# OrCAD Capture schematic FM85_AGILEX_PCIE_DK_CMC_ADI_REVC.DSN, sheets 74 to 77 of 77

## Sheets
74 PWR -VCCCLK_GXR: size B
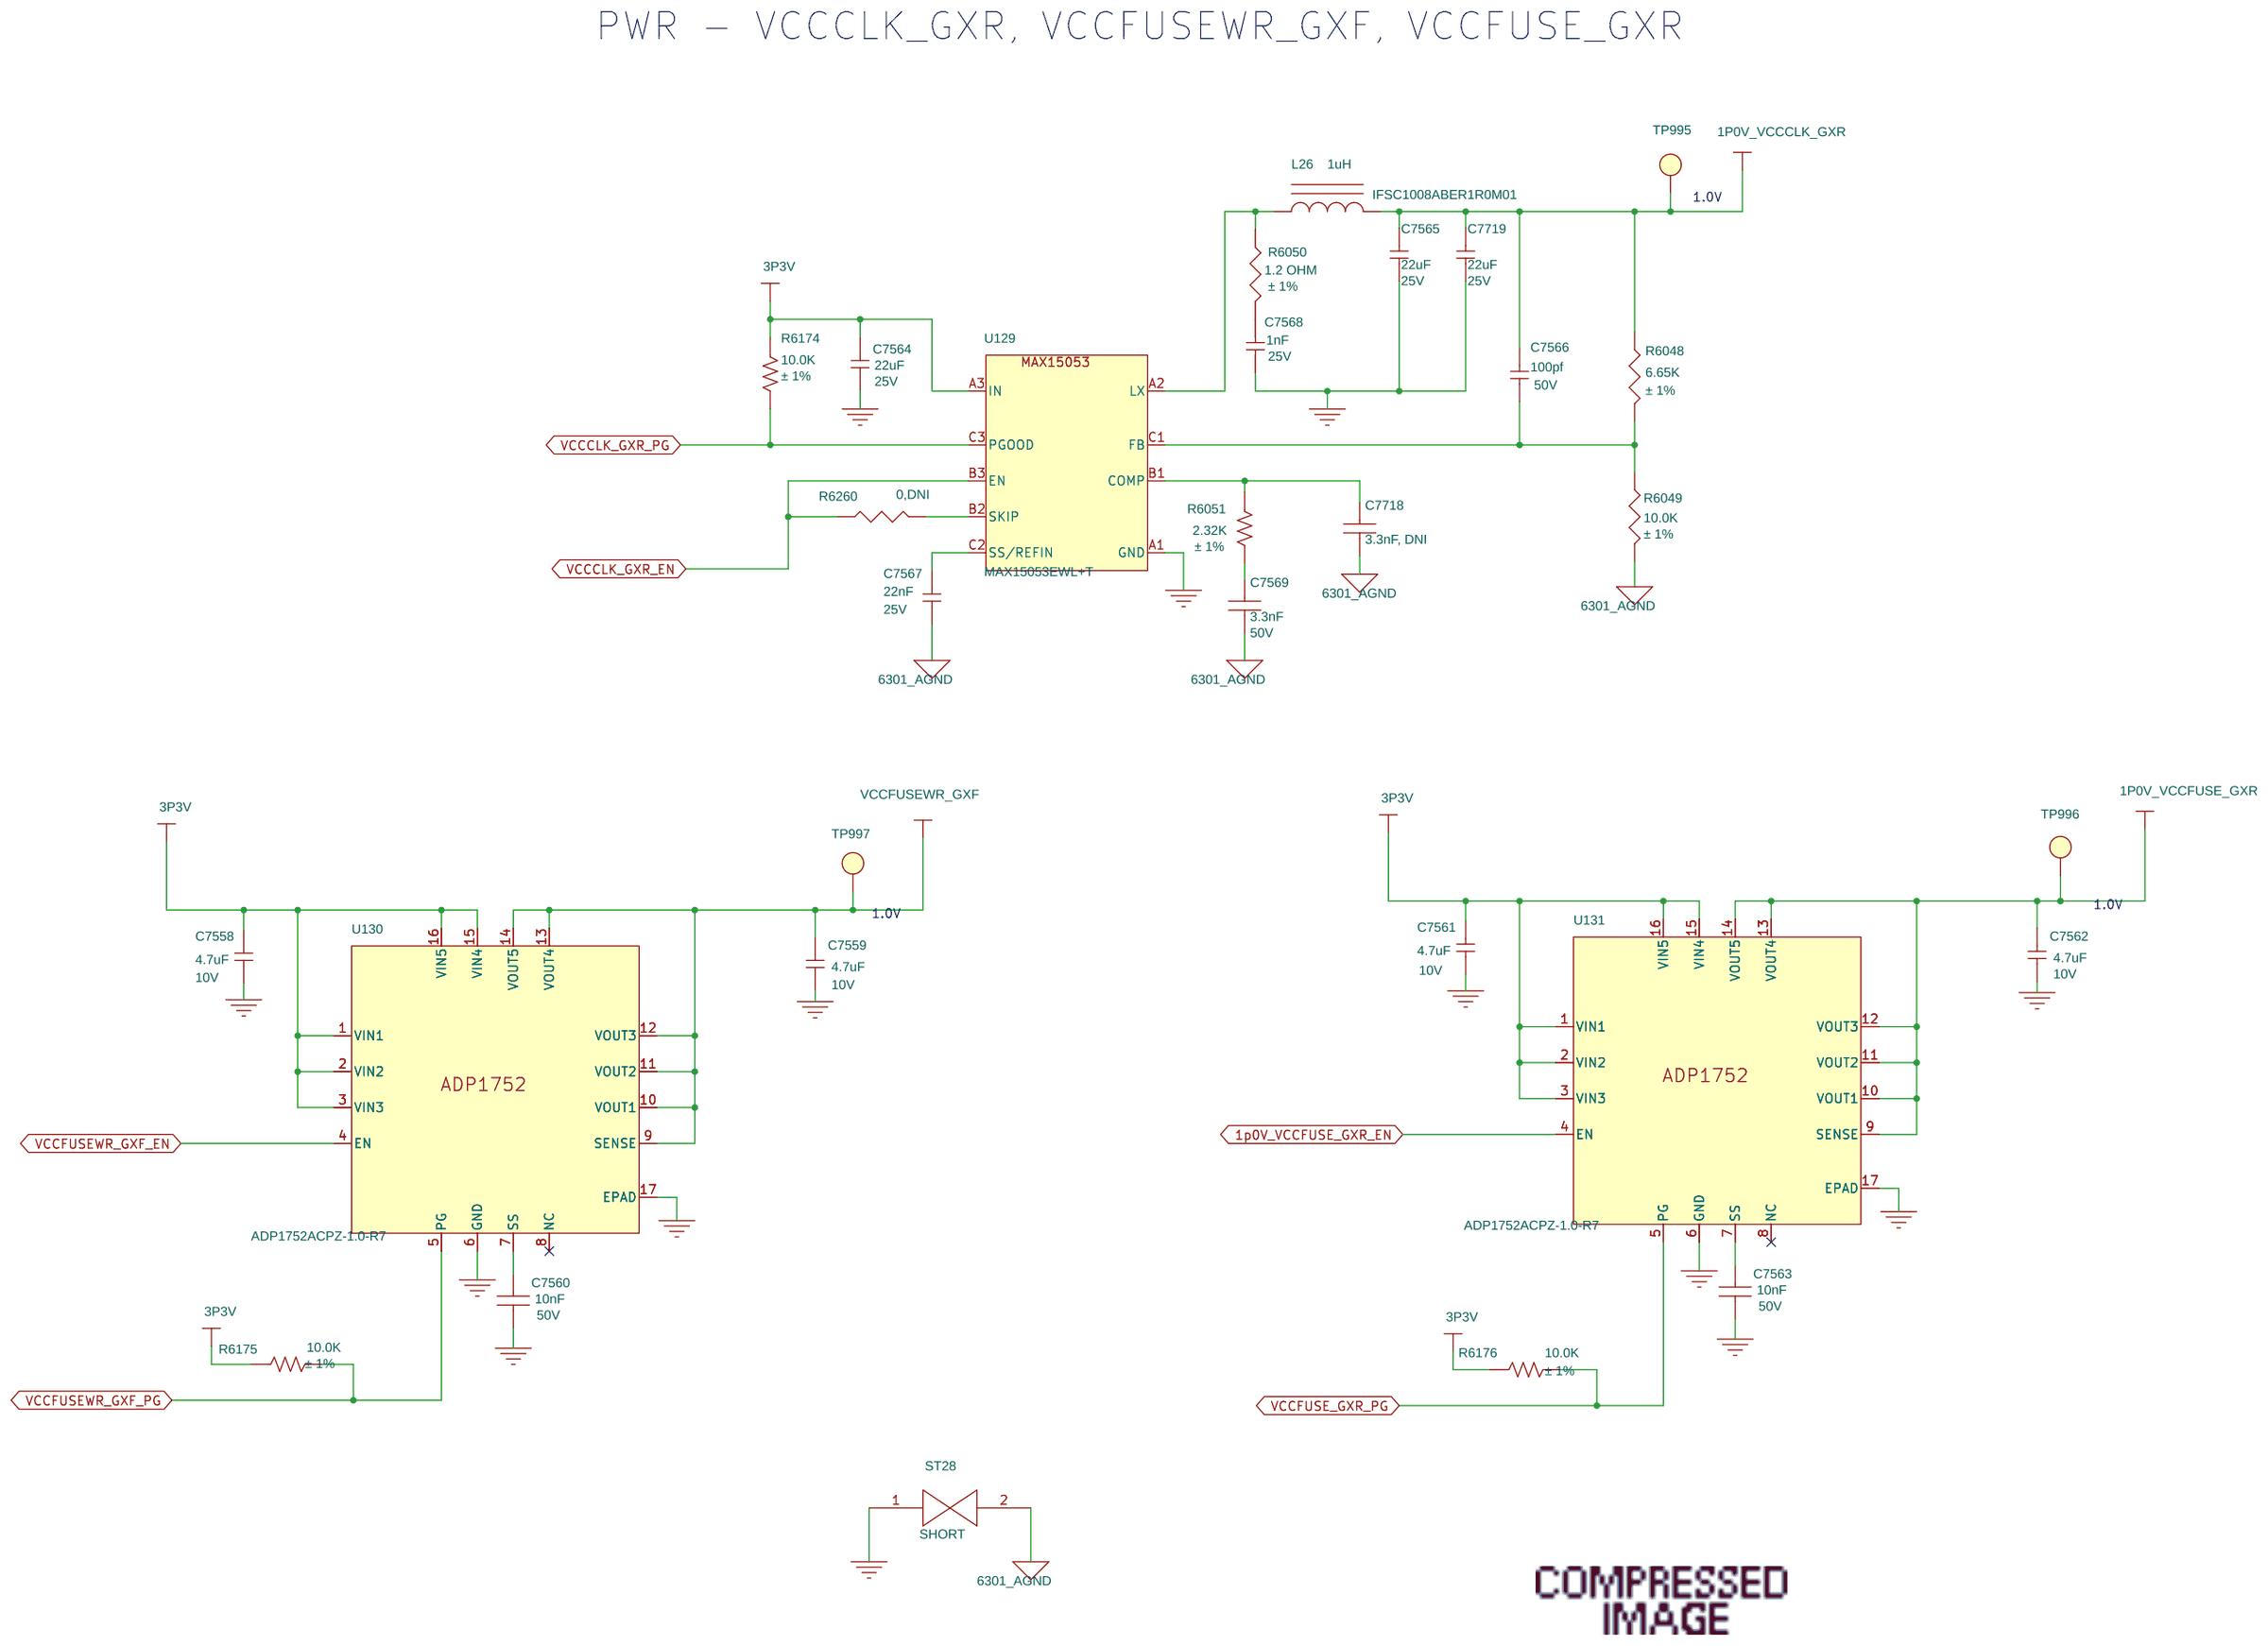
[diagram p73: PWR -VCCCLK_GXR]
75 Decoupling Caps 1: size B
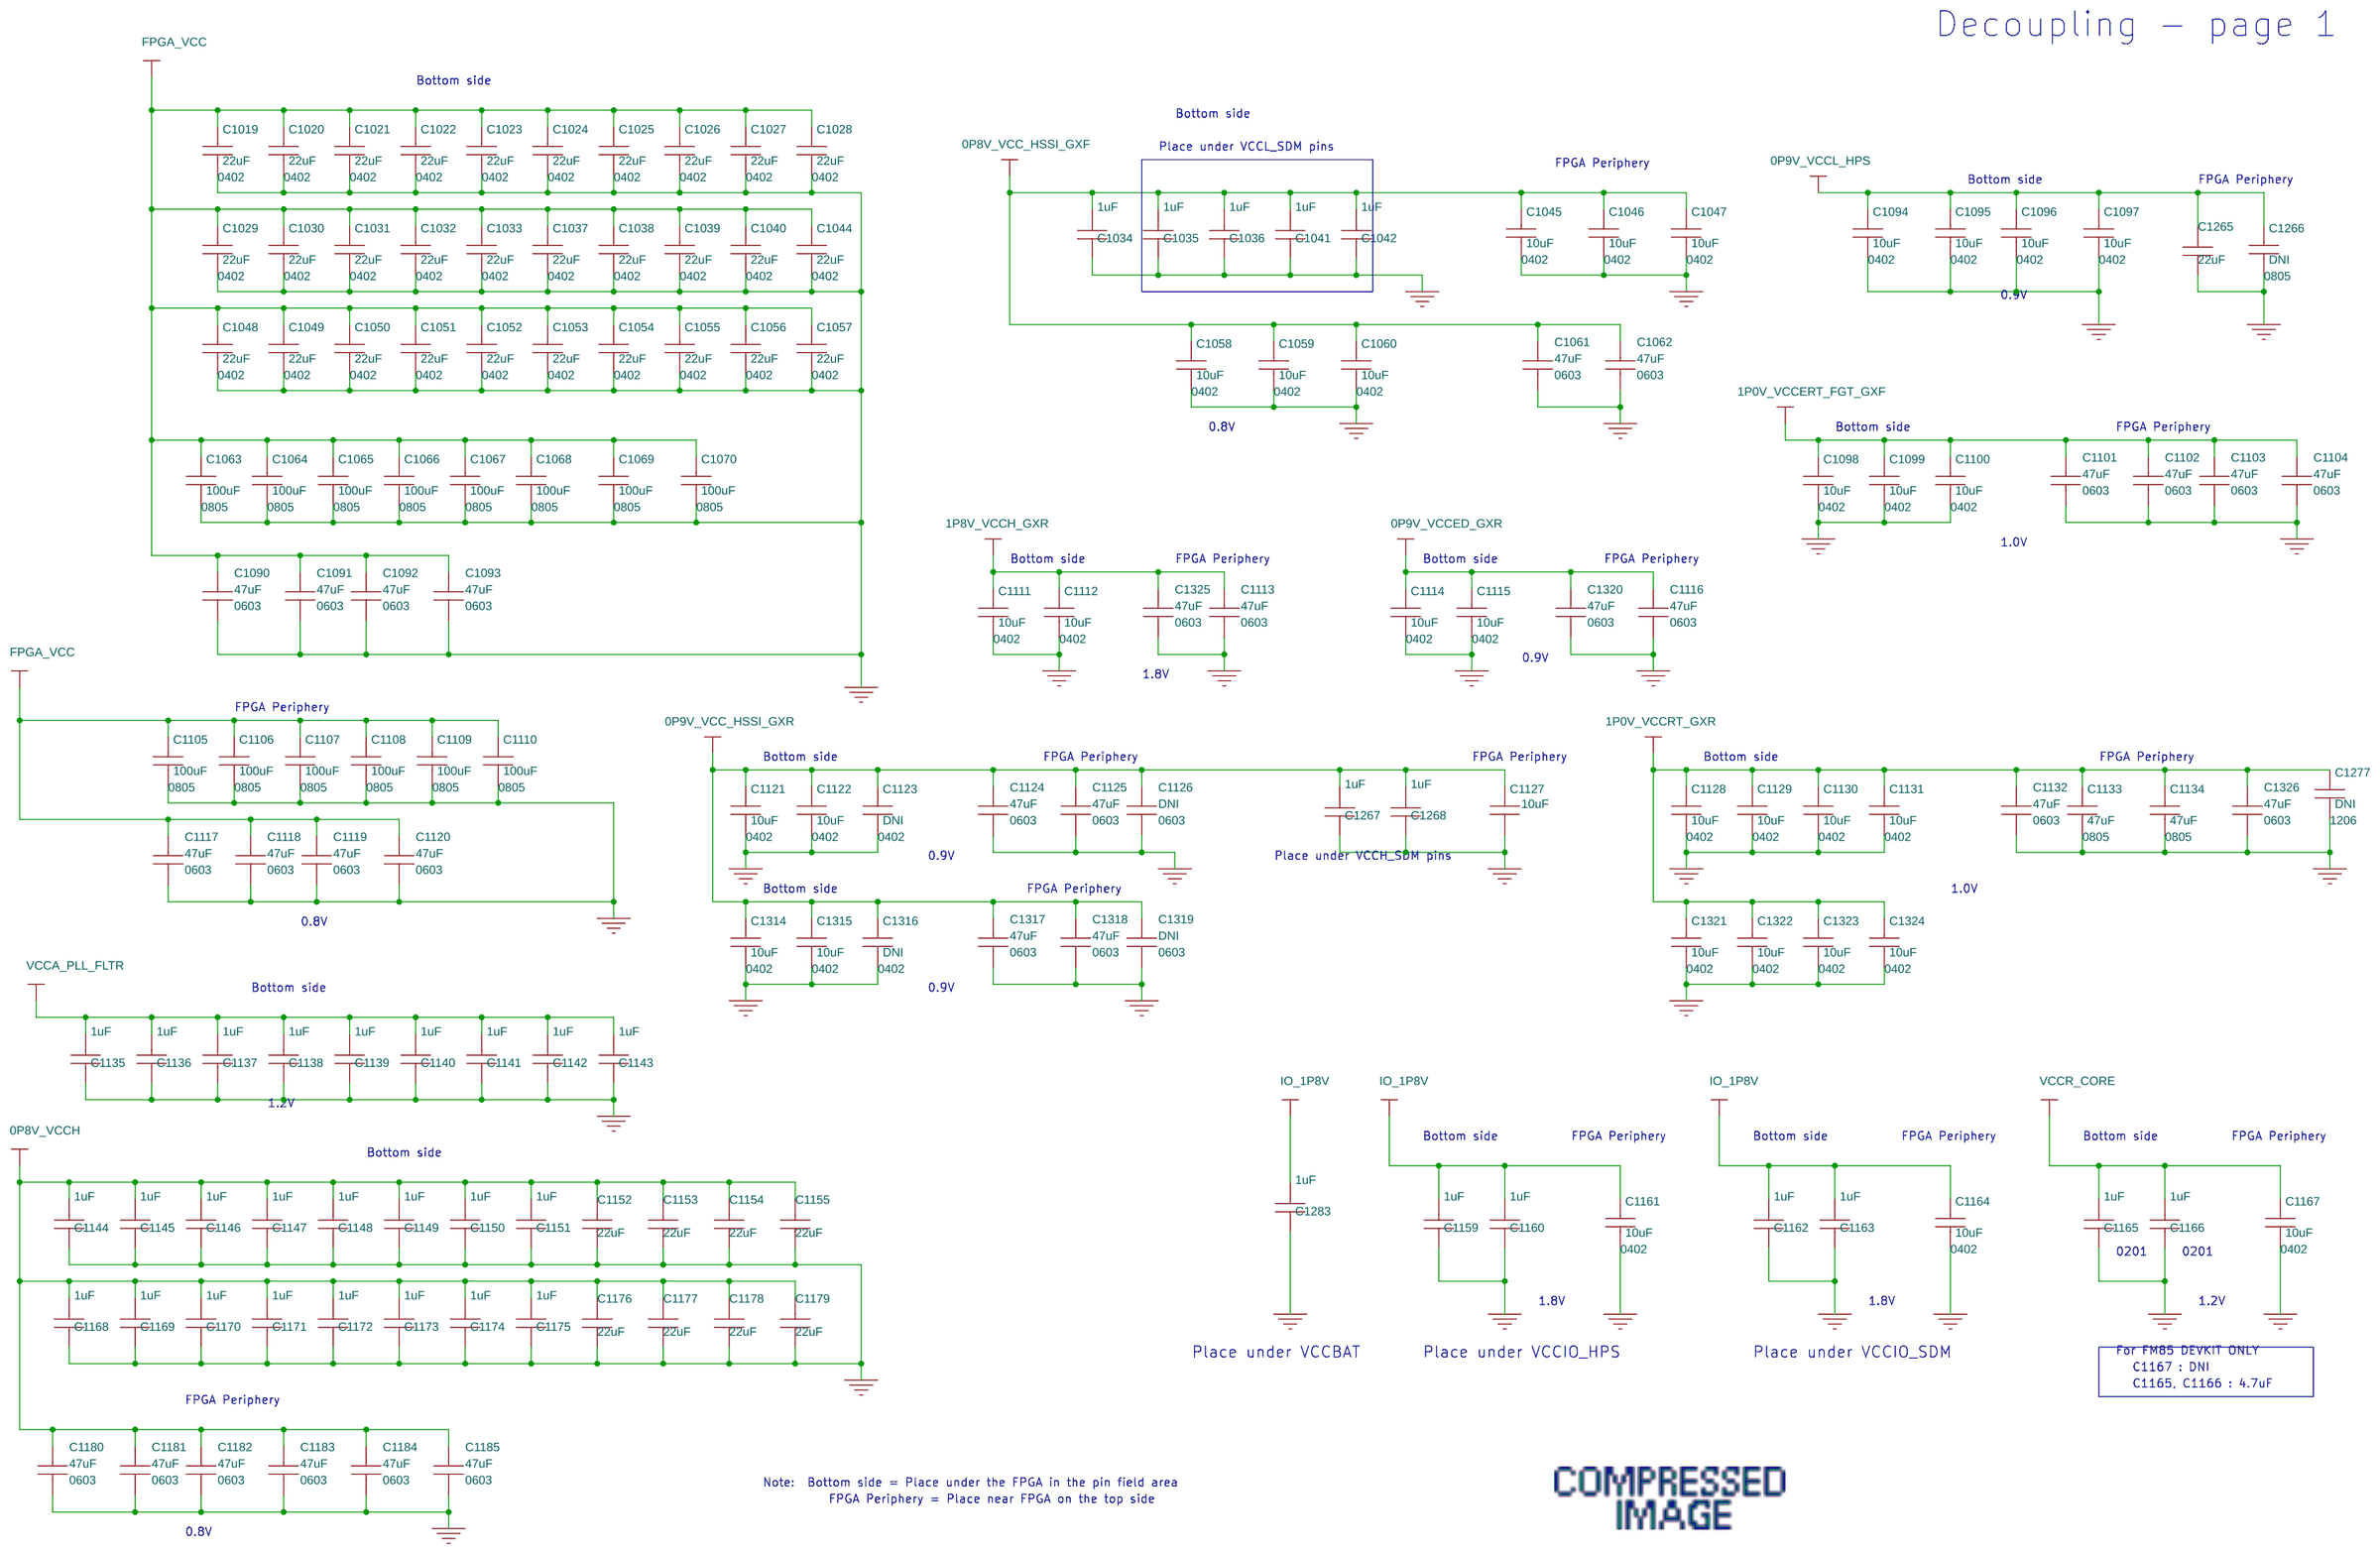
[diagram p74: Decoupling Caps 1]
76 Decoupling Caps 2: size B
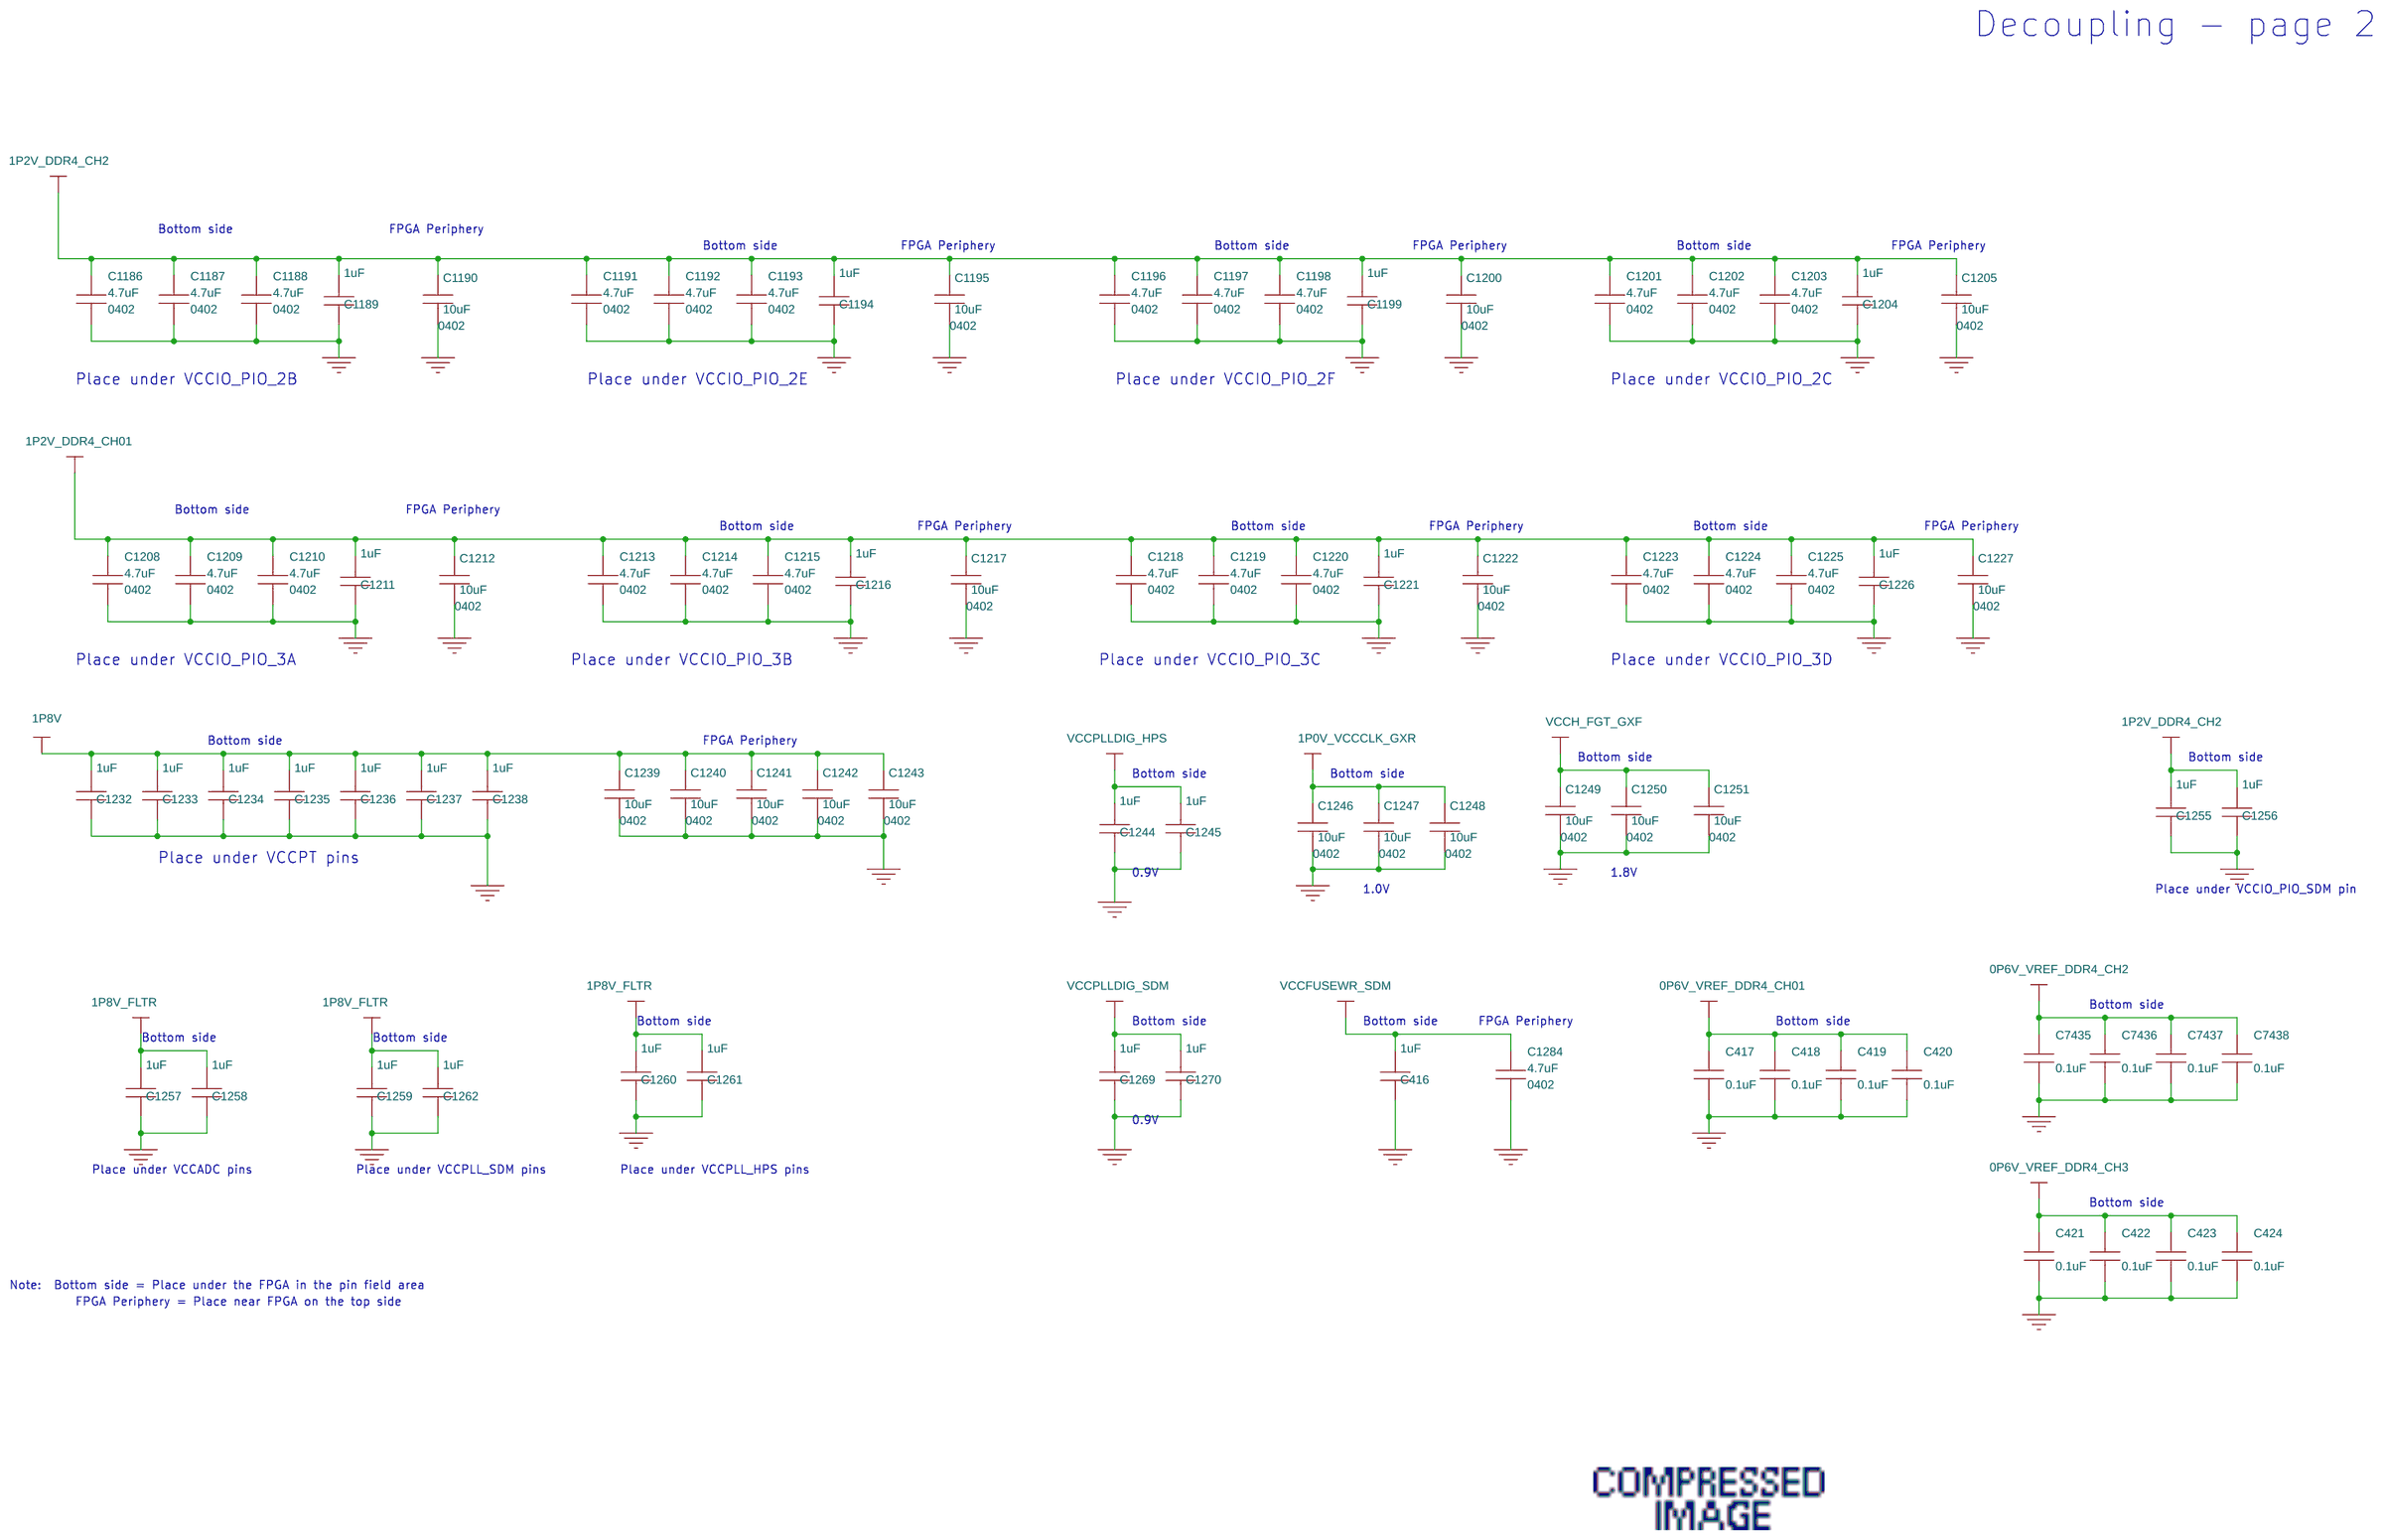
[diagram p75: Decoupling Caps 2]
77 Decoupling Caps 3 &Lev_Shtr: size B
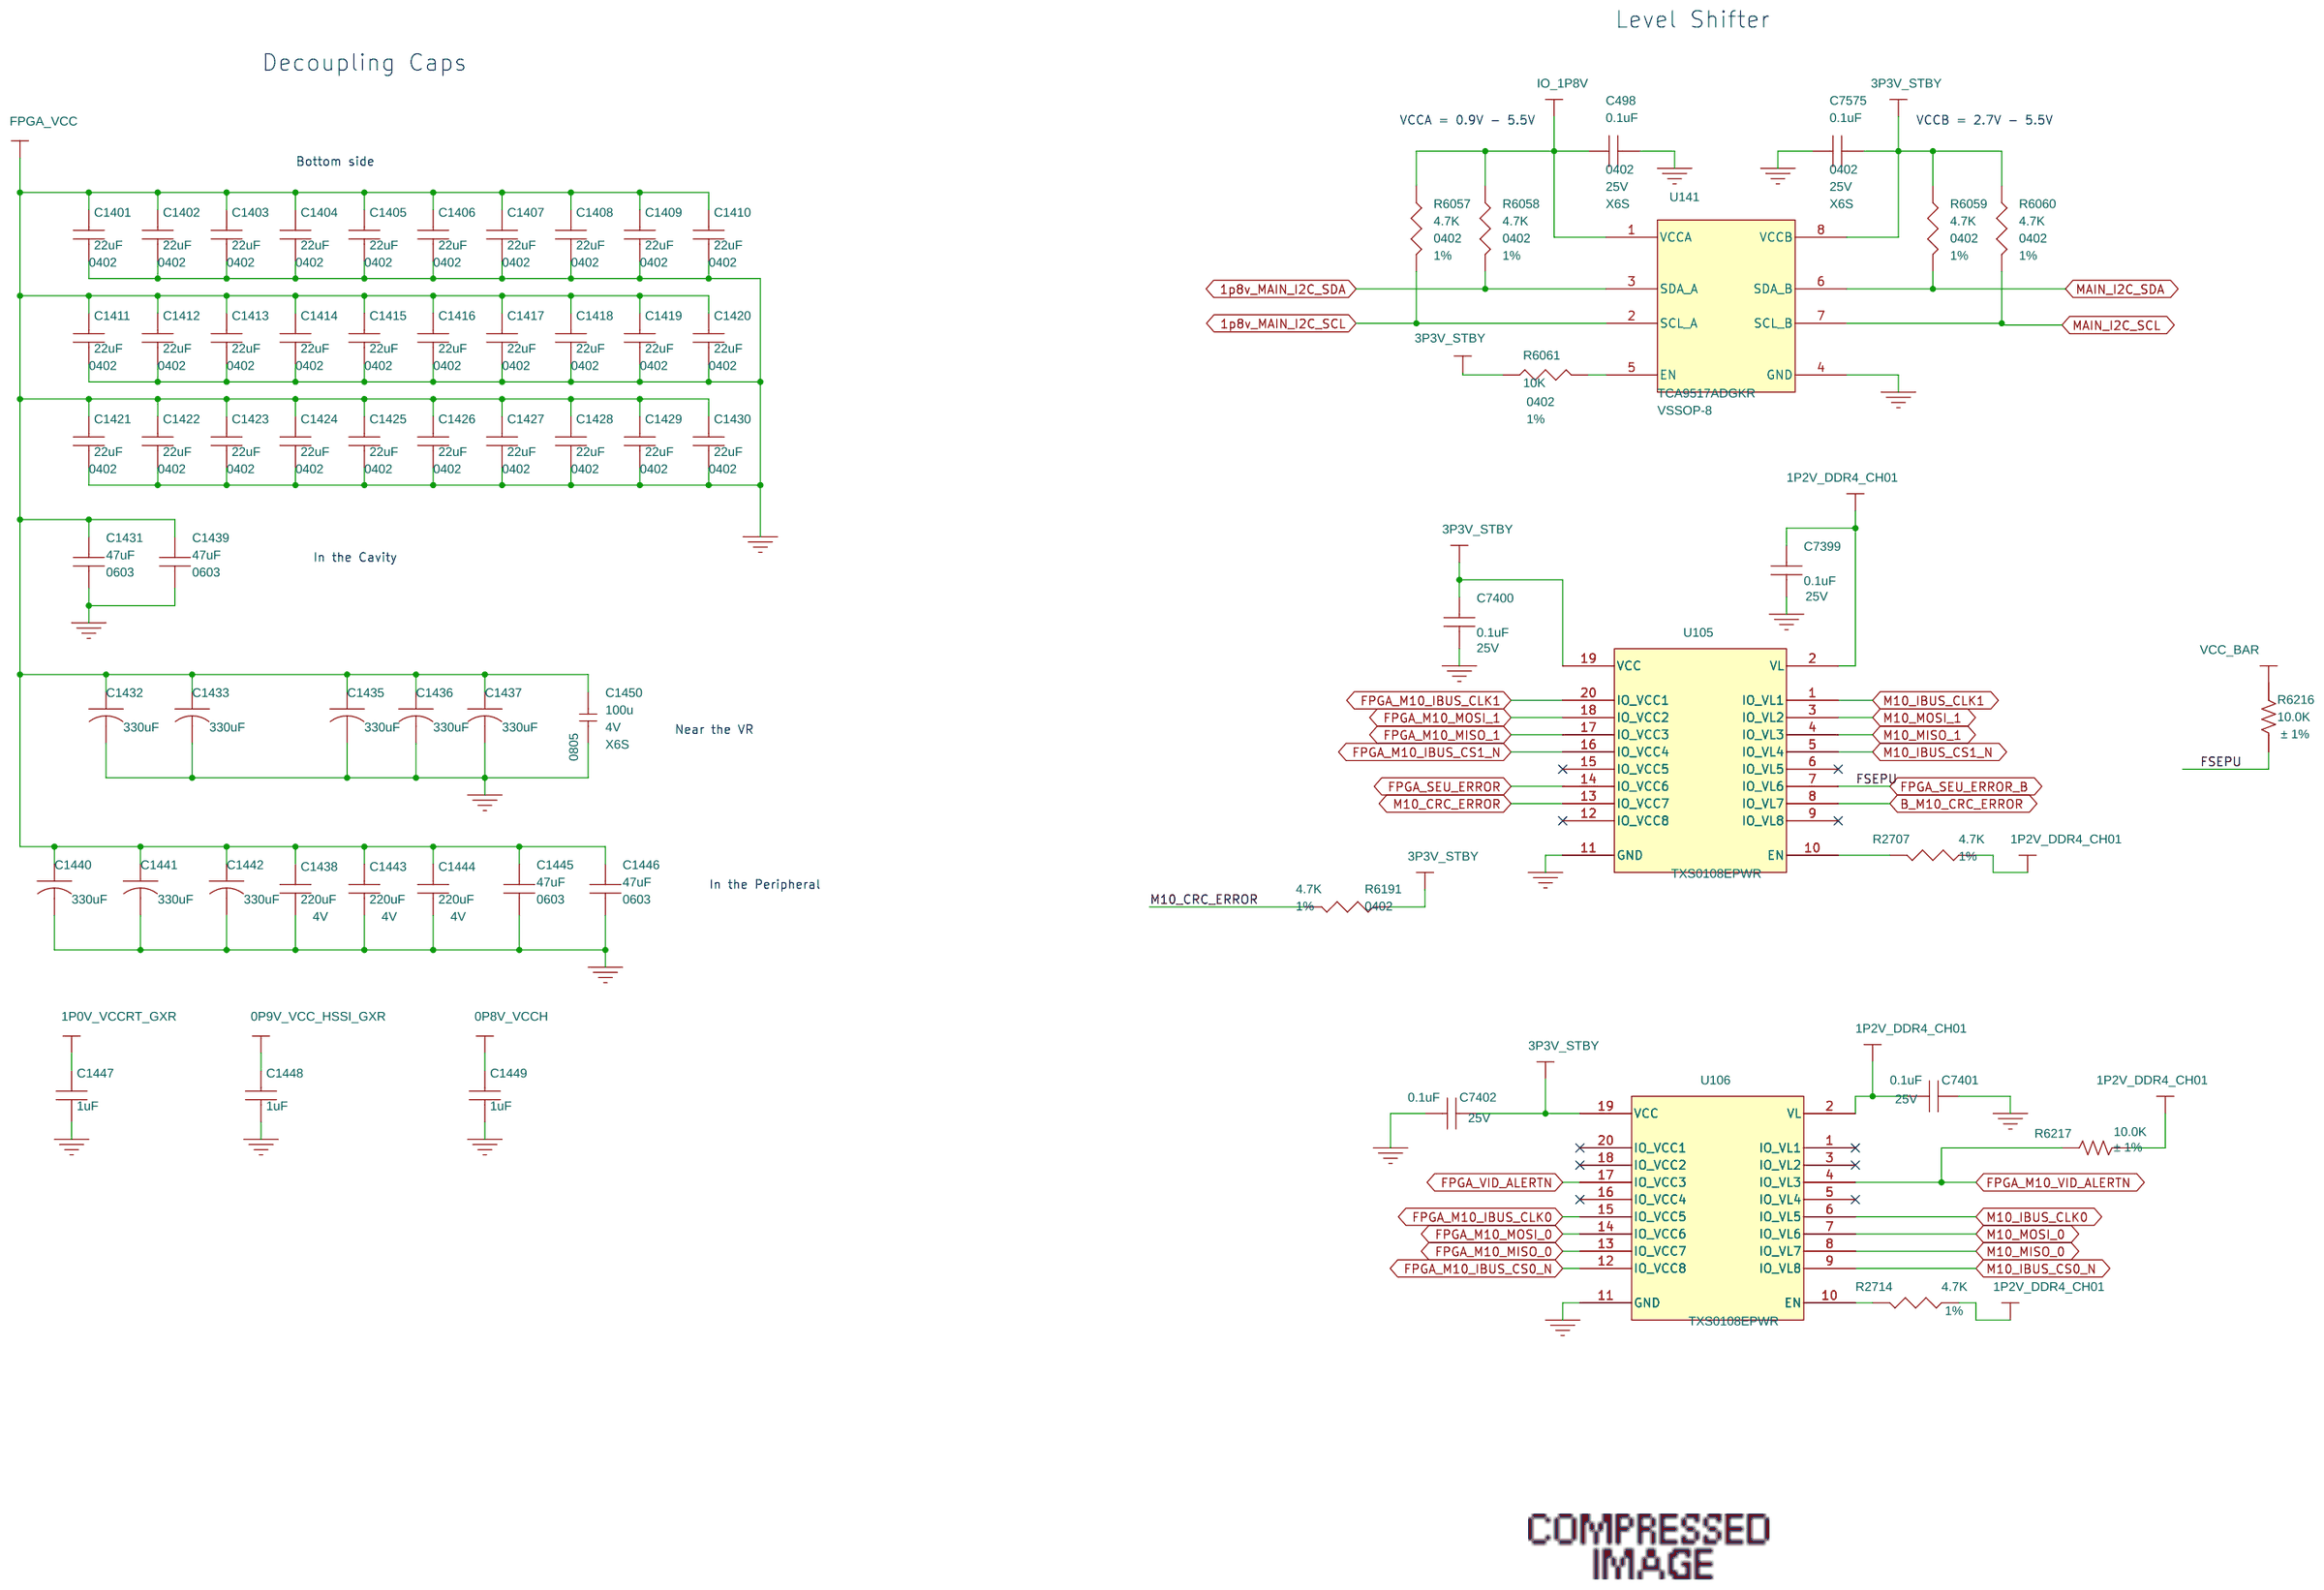
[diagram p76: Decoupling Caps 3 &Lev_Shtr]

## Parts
sheet Decoupling Caps 1
C1019  22uF  [0402]
C1020  22uF  [0402]
C1021  22uF  [0402]
C1022  22uF  [0402]
C1023  22uF  [0402]
C1024  22uF  [0402]
C1025  22uF  [0402]
C1026  22uF  [0402]
C1027  22uF  [0402]
C1028  22uF  [0402]
C1029  22uF  [0402]
C1030  22uF  [0402]
C1031  22uF  [0402]
C1032  22uF  [0402]
C1033  22uF  [0402]
C1034  1uF  [0201]
C1035  1uF  [0201]
C1036  1uF  [0201]
C1037  22uF  [0402]
C1038  22uF  [0402]
C1039  22uF  [0402]
C1040  22uF  [0402]
C1041  1uF  [0201]
C1042  1uF  [0201]
C1044  22uF  [0402]
C1045  10uF  [0402]
C1046  10uF  [0402]
C1047  10uF  [0402]
C1048  22uF  [0402]
C1049  22uF  [0402]
C1050  22uF  [0402]
C1051  22uF  [0402]
C1052  22uF  [0402]
C1053  22uF  [0402]
C1054  22uF  [0402]
C1055  22uF  [0402]
C1056  22uF  [0402]
C1057  22uF  [0402]
C1058  10uF  [0402]
C1059  10uF  [0402]
C1060  10uF  [0402]
C1061  47uF  [0603]
C1062  47uF  [0603]
C1063  100uF  [0805]
C1064  100uF  [0805]
C1065  100uF  [0805]
C1066  100uF  [0805]
C1067  100uF  [0805]
C1068  100uF  [0805]
C1069  100uF  [0805]
C1070  100uF  [0805]
C1090  47uF  [0603]
C1091  47uF  [0603]
C1092  47uF  [0603]
C1093  47uF  [0603]
C1094  10uF  [0402]
C1095  10uF  [0402]
C1096  10uF  [0402]
C1097  10uF  [0402]
C1098  10uF  [0402]
C1099  10uF  [0402]
C1100  10uF  [0402]
C1101  47uF  [0603]
C1102  47uF  [0603]
C1103  47uF  [0603]
C1104  47uF  [0603]
C1105  100uF  [0805]
C1106  100uF  [0805]
C1107  100uF  [0805]
C1108  100uF  [0805]
C1109  100uF  [0805]
C1110  100uF  [0805]
C1111  10uF  [0402]
C1112  10uF  [0402]
C1113  47uF  [0603]
C1114  10uF  [0402]
C1115  10uF  [0402]
C1116  47uF  [0603]
C1117  47uF  [0603]
C1118  47uF  [0603]
C1119  47uF  [0603]
C1120  47uF  [0603]
C1121  10uF  [0402]
C1122  10uF  [0402]
C1123  DNI  [0402]
C1124  47uF  [0603]
C1125  47uF  [0603]
C1126  DNI  [0603]
C1127  10uF  [0402]
C1128  10uF  [0402]
C1129  10uF  [0402]
C1130  10uF  [0402]
C1131  10uF  [0402]
C1132  47uF  [0603]
C1133  47uF  [0805]
C1134  47uF  [0805]
C1135  1uF  [0201]
C1136  1uF  [0201]
C1137  1uF  [0201]
C1138  1uF  [0201]
C1139  1uF  [0201]
C1140  1uF  [0201]
C1141  1uF  [0201]
C1142  1uF  [0201]
C1143  1uF  [0201]
C1144  1uF  [0201]
C1145  1uF  [0201]
C1146  1uF  [0201]
C1147  1uF  [0201]
C1148  1uF  [0201]
C1149  1uF  [0201]
C1150  1uF  [0201]
C1151  1uF  [0201]
C1152  22uF  [0603]
C1153  22uF  [0603]
C1154  22uF  [0603]
C1155  22uF  [0603]
C1159  1uF  [0201]
C1160  1uF  [0201]
C1161  10uF  [0402]
C1162  1uF  [0201]
C1163  1uF  [0201]
C1164  10uF  [0402]
C1165  1uF  [0201]
C1166  1uF  [0201]
C1167  10uF  [0402]
C1168  1uF  [0201]
C1169  1uF  [0201]
C1170  1uF  [0201]
C1171  1uF  [0201]
C1172  1uF  [0201]
C1173  1uF  [0201]
C1174  1uF  [0201]
C1175  1uF  [0201]
C1176  22uF  [0603]
C1177  22uF  [0603]
C1178  22uF  [0603]
C1179  22uF  [0603]
C1180  47uF  [0603]
C1181  47uF  [0603]
C1182  47uF  [0603]
C1183  47uF  [0603]
C1184  47uF  [0603]
C1185  47uF  [0603]
C1265  22uF  [0603]
C1266  DNI  [0805]
C1267  1uF  [0201]
C1268  1uF  [0201]
C1277  DNI  [1206]
C1283  1uF  [0201]
C1314  10uF  [0402]
C1315  10uF  [0402]
C1316  DNI  [0402]
C1317  47uF  [0603]
C1318  47uF  [0603]
C1319  DNI  [0603]
C1320  47uF  [0603]
C1321  10uF  [0402]
C1322  10uF  [0402]
C1323  10uF  [0402]
C1324  10uF  [0402]
C1325  47uF  [0603]
C1326  47uF  [0603]
sheet Decoupling Caps 2
C416  1uF  [0201]
C417  0.1uF  [0402]
C418  0.1uF  [0402]
C419  0.1uF  [0402]
C420  0.1uF  [0402]
C421  0.1uF  [0402]
C422  0.1uF  [0402]
C423  0.1uF  [0402]
C424  0.1uF  [0402]
C1186  4.7uF  [0402]
C1187  4.7uF  [0402]
C1188  4.7uF  [0402]
C1189  1uF  [0201]
C1190  10uF  [0402]
C1191  4.7uF  [0402]
C1192  4.7uF  [0402]
C1193  4.7uF  [0402]
C1194  1uF  [0201]
C1195  10uF  [0402]
C1196  4.7uF  [0402]
C1197  4.7uF  [0402]
C1198  4.7uF  [0402]
C1199  1uF  [0201]
C1200  10uF  [0402]
C1201  4.7uF  [0402]
C1202  4.7uF  [0402]
C1203  4.7uF  [0402]
C1204  1uF  [0201]
C1205  10uF  [0402]
C1208  4.7uF  [0402]
C1209  4.7uF  [0402]
C1210  4.7uF  [0402]
C1211  1uF  [0201]
C1212  10uF  [0402]
C1213  4.7uF  [0402]
C1214  4.7uF  [0402]
C1215  4.7uF  [0402]
C1216  1uF  [0201]
C1217  10uF  [0402]
C1218  4.7uF  [0402]
C1219  4.7uF  [0402]
C1220  4.7uF  [0402]
C1221  1uF  [0201]
C1222  10uF  [0402]
C1223  4.7uF  [0402]
C1224  4.7uF  [0402]
C1225  4.7uF  [0402]
C1226  1uF  [0201]
C1227  10uF  [0402]
C1232  1uF  [0201]
C1233  1uF  [0201]
C1234  1uF  [0201]
C1235  1uF  [0201]
C1236  1uF  [0201]
C1237  1uF  [0201]
C1238  1uF  [0201]
C1239  10uF  [0402]
C1240  10uF  [0402]
C1241  10uF  [0402]
C1242  10uF  [0402]
C1243  10uF  [0402]
C1244  1uF  [0201]
C1245  1uF  [0201]
C1246  10uF  [0402]
C1247  10uF  [0402]
C1248  10uF  [0402]
C1249  10uF  [0402]
C1250  10uF  [0402]
C1251  10uF  [0402]
C1255  1uF  [0201]
C1256  1uF  [0201]
C1257  1uF  [0201]
C1258  1uF  [0201]
C1259  1uF  [0201]
C1260  1uF  [0201]
C1261  1uF  [0201]
C1262  1uF  [0201]
C1269  1uF  [0201]
C1270  1uF  [0201]
C1284  4.7uF  [0402]
C7435  0.1uF  [0402]
C7436  0.1uF  [0402]
C7437  0.1uF  [0402]
C7438  0.1uF  [0402]
sheet Decoupling Caps 3 &Lev_Shtr
C498  0.1uF  [0402]
C1401  22uF  [0402]
C1402  22uF  [0402]
C1403  22uF  [0402]
C1404  22uF  [0402]
C1405  22uF  [0402]
C1406  22uF  [0402]
C1407  22uF  [0402]
C1408  22uF  [0402]
C1409  22uF  [0402]
C1410  22uF  [0402]
C1411  22uF  [0402]
C1412  22uF  [0402]
C1413  22uF  [0402]
C1414  22uF  [0402]
C1415  22uF  [0402]
C1416  22uF  [0402]
C1417  22uF  [0402]
C1418  22uF  [0402]
C1419  22uF  [0402]
C1420  22uF  [0402]
C1421  22uF  [0402]
C1422  22uF  [0402]
C1423  22uF  [0402]
C1424  22uF  [0402]
C1425  22uF  [0402]
C1426  22uF  [0402]
C1427  22uF  [0402]
C1428  22uF  [0402]
C1429  22uF  [0402]
C1430  22uF  [0402]
C1431  47uF  [0603]
C1432  330uF  [3528_2MM]
C1433  330uF  [3528_2MM]
C1435  330uF  [3528_2MM]
C1436  330uF  [3528_2MM]
C1437  330uF  [3528_2MM]
C1438  220uF  [1206]
C1439  47uF  [0603]
C1440  330uF  [3528_2MM]
C1441  330uF  [3528_2MM]
C1442  330uF  [3528_2MM]
C1443  220uF  [1206]
C1444  220uF  [1206]
C1445  47uF  [0603]
C1446  47uF  [0603]
C1447  1uF  [0201]
C1448  1uF  [0201]
C1449  1uF  [0201]
C1450  100u  [CAPC2012X110L50L]
C7399  0.1uF  [0402]
C7400  0.1uF  [0402]
C7401  0.1uF  [0402]
C7402  0.1uF  [0402]
C7575  0.1uF  [0402]
R2707  4.7K  [0402]
R2714  4.7K  [0402]
R6057  4.7K  [0402]
R6058  4.7K  [0402]
R6059  4.7K  [0402]
R6060  4.7K  [0402]
R6061  10K  [0402]
R6191  4.7K  [0402]
R6216  10.0K  [0402]
R6217  10.0K  [0402]
U105  TXS0108EPWR  [20-TSSOP]
U106  TXS0108EPWR  [20-TSSOP]
U141  TCA9517ADGKR  [VSSOP-8]
sheet PWR -VCCCLK_GXR
C7558  4.7uF  [0402]
C7559  4.7uF  [0402]
C7560  10nF  [0402]
C7561  4.7uF  [0402]
C7562  4.7uF  [0402]
C7563  10nF  [0402]
C7564  22uF  [1206]
C7565  22uF  [1206]
C7566  100pf  [0402]
C7567  22nF  [0402]
C7568  1nF  [0402]
C7569  3.3nF  [0402]
C7718  3.3nF, DNI  [0402]
C7719  22uF  [1206]
L26  1uH  [IFSC1008ABER1R0M01]
R6048  6.65K  [0402]
R6049  10.0K  [0402]
R6050  1.2 OHM  [RC0402]
R6051  2.32K  [0402]
R6174  10.0K  [0402]
R6175  10.0K  [0402]
R6176  10.0K  [0402]
R6260  0,DNI  [0402]
ST28  SHORT  [SHORT]
TP995  TESTPOINT  [30MIL_TP]
TP996  TESTPOINT  [30MIL_TP]
TP997  TESTPOINT  [30MIL_TP]
U129  MAX15053EWL+T  [BGA9N50P3X3_149X149X69N]
U130  ADP1752ACPZ-1.0-R7  [QFN65P400X400X80-17NA]
U131  ADP1752ACPZ-1.0-R7  [QFN65P400X400X80-17NA]

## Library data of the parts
C1019-C1033 C1037-C1040 C1044 C1048-C1057 C1401-C1430 = CAP: CAPC,X5R,0402,22.00UF,4.00V,+/- 20%; Item Num: A36096-179; Lead Free Status: Lead Free; Manufacturer: Taiyo Yuden; Manufacturer Part Num: AMK105EBJ226MV-F; Num Pins: 2; PART_SUBCLASS: CAPACITORS; Part Class: CAPACITORS; RATED_VOLTAGE: 4.0V; RoHS Compliant: RoHS Compliant; Temperature Coefficient: X5R
C416 C1034-C1036 C1041 C1042 C1135-C1151 C1159 C1160 C1162 C1163 C1168-C1175 C1189 C1194 C1199 C1204 C1211 C1216 C1221 C1226 C1232-C1238 C1244 C1245 C1255-C1262 C1267-C1270 C1283 = CAP: CAP - CER 1UF 6.3V 20% X5R 0201; Item Num: C83410-013; Lead Free Status: Yes; Manufacturer: TDK; Manufacturer Part Num: C0603X5R0J105M; Num Pins: 2; Part Class: CAPACITORS; RoHS Compliant: Yes
C1045-C1047 C1058-C1060 C1094-C1100 C1111 C1112 C1114 C1115 C1121 C1122 C1127-C1131 C1161 C1164 C1167 C1190 C1195 C1200 C1205 C1212 C1217 C1222 C1227 C1239-C1243 C1246-C1251 C1314 C1315 C1321-C1324 = CAP: CAP CER 10UF 6.3V X5R 0402; Item Num: K46607-001; Lead Free Status: Lead Free; Manufacturer: Murata Electronics North America; Manufacturer Part Num: GRJ155R60J106ME11D; Num Pins: 2; PART_SUBCLASS: CAPACITORS; Part Class: CAPACITORS; RATED_VOLTAGE: 6.3V; RoHS Compliant: RoHS Compliant; Temperature Coefficient: X5R
C1061 C1062 C1090-C1093 C1101-C1104 C1113 C1116-C1120 C1124 C1125 C1132 C1180-C1185 C1317 C1318 C1320 C1325 C1326 C1431 C1439 C1445 C1446 = CAP: CAP CER 47UF 6.3V X5R 0603; Item Num: K31624-001; MFR_LIFECYCLE: Active; Manufacturer: Murata Electronics North America; Manufacturer Part Num: GRM188R60J476ME15D; Num Pins: 2; PART_SUBCLASS: CAPACITORS; RATED_VOLTAGE: 6.3V; RoHS Compliant: RoHS Compliant; TOLERANCE: 20%
C1063-C1070 C1105-C1110 = CAP: CAP CER 100UF 6.3V X5R 0805; Item Num: K32109-001; Lead Free Status: Lead Free; Manufacturer: Murata Electronics North America; Manufacturer Part Num: GRM21BR60J107ME15L; Num Pins: 2; PART_SUBCLASS: CAPACITORS; Part Class: CAPACITORS; RATED_VOLTAGE: 6.3V; RoHS Compliant: RoHS Compliant; Temperature Coefficient: X5R
C1123 C1316 = CAP: CAP CER 10UF 6.3V X5R 0402; CAPACITANCE: 10uF; Item Num: K46607-001; Lead Free Status: Lead Free; Manufacturer: Murata Electronics North America; Manufacturer Part Num: GRJ155R60J106ME11D; Num Pins: 2; PART_SUBCLASS: CAPACITORS; Part Class: CAPACITORS; RATED_VOLTAGE: 6.3V; RoHS Compliant: RoHS Compliant; Temperature Coefficient: X5R
C1126 C1319 = CAP: CAP CER 47UF 6.3V X5R 0603; CAPACITANCE: 47uF; Item Num: K31624-001; MFR_LIFECYCLE: Active; Manufacturer: Murata Electronics North America; Manufacturer Part Num: GRM188R60J476ME15D; Num Pins: 2; PART_SUBCLASS: CAPACITORS; RATED_VOLTAGE: 6.3V; RoHS Compliant: RoHS Compliant; TOLERANCE: 20%
C1133 C1134 = CAP: CAP CER 47UF 6.3V X5R 0805; Item Num: G10490-001; Lead Free Status: Lead Free; Manufacturer: Murata Electronics North America; Manufacturer Part Num: GRM21BR60J476ME15L; Num Pins: 2; PART_SUBCLASS: CAPACITORS; Part Class: CAPACITORS; RATED_VOLTAGE: 6.3V; RoHS Compliant: RoHS Compliant; Temperature Coefficient: X5R
C1152-C1155 C1176-C1179 C1265 = CAP: CAP CER 22UF 6.3V X6S 0603; AGILE_LINK: http://sj-agile9app/Agile/PLMServlet?action=OpenEmailObject&classid=10000&objid=257560276; Item Num: H63299-001; LIFECYCLE_PHASE: Active; Lead Free Status: Not Lead Free; MFR_LIFECYCLE: Active; Manufacturer: Murata; Manufacturer Part Num: GRM188C80J226ME15D; Num Pins: 2; PART_SUBCLASS: CAPACITORS; RATED_VOLTAGE: 6.3V; RoHS Compliant: RoHS Compliant; TOLERANCE: 20%; Temperature Coefficient: X6S
C1165 C1166 = CAP: CAP - CER 1UF 6.3V 20% X5R 0201; Item Num: H57538-002; Lead Free Status: Yes; Manufacturer: TDK; Manufacturer Part Num: C0603X5R0J105M; Num Pins: 2; Part Class: CAPACITORS; RoHS Compliant: Yes
C1266 = CAP: CAP CER 100UF 6.3V X5R 0805; CAPACITANCE: 100uF; Item Num: K32109-001; Lead Free Status: Lead Free; Manufacturer: Murata Electronics North America; Manufacturer Part Num: GRM21BR60J107ME15L; Num Pins: 2; PART_SUBCLASS: CAPACITORS; Part Class: CAPACITORS; RATED_VOLTAGE: 6.3V; RoHS Compliant: RoHS Compliant; Temperature Coefficient: X5R
C1277 = CAP: CAP CER 220UF 4V X5R 1206; CAPACITANCE: 220uF; Item Num: C34226-004; Lead Free Status: Lead Free; Manufacturer: Murata Electronics North America; Manufacturer Part Num: GRM31CR60G227ME11L; Num Pins: 2; PART_SUBCLASS: CAPACITORS; Part Class: CAPACITORS; RATED_VOLTAGE: 4V; RoHS Compliant: RoHS Compliant; Temperature Coefficient: X5R
C417-C424 C7435-C7438 = CAP: CAPC,  X7R, 0402, 0.1uF, 25V, ±20%; Dielectric: Y5V; Item Num: K13660-001; LIFECYCLE_PHASE: Active; Lead Free Status: Lead Free; MFR_LIFECYCLE: Active; Manufacturer: Murata; Manufacturer Part Num: GRM155R71E104KE14D; Num Pins: 2; PART_SUBCLASS: CAPACITORS; Part Class: CAPACITORS; RATED_VOLTAGE: 25V; RoHS Compliant: RoHS Compliant; Tolerance: +80%/-20%
C1186-C1188 C1191-C1193 C1196-C1198 C1201-C1203 C1208-C1210 C1213-C1215 C1218-C1220 C1223-C1225 C1284 = CAP: CAP - CER 4.7UF, +/-20%, 6.3V, X5R, 0402; Item Num: A36096-107; Manufacturer: Murata; Manufacturer Part Num: GRM155R60J475ME87D; Tolerance: +/-20%; Voltage: 6.3V
C498 C7575 = CAP: CAP CER 0.1UF 25V X6S 0402; Dielectric: X6S; Item Num: K19434-001; LIFECYCLE_PHASE: Active; Lead Free Status: Lead Free; Manufacturer: Murata; Manufacturer Part Num: GRM155C81E104KA12D; Num Pins: 2; Part Class: CAPACITORS; RATED_VOLTAGE: 25V; RoHS Compliant: RoHS Compliant; Tolerance: 10%
C1432 C1433 C1435-C1437 C1440-C1442 = PCAP: POSCAP, B2, PWR, 330UF,2.5V; AGILE_LINK: http://sj-agile9app/Agile/PLMServlet?action=OpenEmailObject&classid=10000&objid=257237054; Item Num: G63608-001; LIFECYCLE_PHASE: Active; Lead Free Status: Lead Free; MFR_LIFECYCLE: Active; Manufacturer: Panasonic; Manufacturer Part Num: ETPE330M9GB; Num Pins: 2; PART_SUBCLASS: CAPACITORS; RATED_VOLTAGE: 2.5V; RoHS Compliant: RoHS Compliant; TOLERANCE: 20%; Type: Poscap
C1438 C1443 C1444 = CAP: CAP CER 220UF 4V X6S 1206,+/- 20%; Item Num: K33438-001; Manufacturer: Murata; Manufacturer Part Num: GRM31CC80G227ME11L; Tolerance: +/-20%; Voltage: 4V
C1447-C1449 = CAP: CAPC,X5R,0201,1.00UF,6.3V,+/- 20%; Item Num: C83410-013; Lead Free Status: Yes; Manufacturer: MURATA; Manufacturer Part Num: GRM033R60J105MEA2D; Num Pins: 2; Part Class: CAPACITORS; RoHS Compliant: Yes
C1450 = Cap,_NP,_0805: CAPC,X6S,0805,100.00UF,4.00V,+/- 20%; Dielectric: X6S; Item Num: H94455-002; Manufacturer: Murata; Manufacturer Part Num: GRM21BC80G107ME15L; Package: 0805; Part Number: GRM21BC80G107ME15L; WVDC: 4V
C7399-C7402 = CAP: CAPC,  X7R, 0402, 0.1uF, 25V, ±20%; Item Num: K13660-001; LIFECYCLE_PHASE: Active; Lead Free Status: Lead Free; MFR_LIFECYCLE: Active; Manufacturer: Murata; Manufacturer Part Num: GRM155R71E104KE14D; Num Pins: 2; PART_SUBCLASS: CAPACITORS; Part Class: CAPACITORS; RATED_VOLTAGE: 25V; RoHS Compliant: RoHS Compliant; Tolerance: +80%/-20%
R2707 R2714 = RESISTOR: RES,4.70K OHMS,1.0%,1/16W,0402; Item Num: A93548-517; Lead Free Status: No; Manufacturer: Vishay; Manufacturer Part Num: CRCW04024K70FKED; Manufacturer's Part No.: CRCW04024K70FKED; Num Pins: 2; Part Class: RESISTORS; Price: 0; RoHS Compliant: Yes; TOLERANCE: 1%
R6057-R6060 = RESISTOR: RES,4.70K OHMS,1.0%,1/16W,0402; AGILE_LINK: http://sj-agile9app/Agile/PLMServlet?action=OpenEmailObject&classid=10000&objid=146753272; Item Num: A93548-517; LIFECYCLE_PHASE: Active; Lead Free Status: No; MFR_LIFECYCLE: Active; Manufacturer: Vishay; Manufacturer Part Num: CRCW04024K70FKED; Num Pins: 2; PART_SUBCLASS: RESISTORS; POWER: 1/16W; RoHS Compliant: Yes; TOLERANCE: 1%
R6061 = RESISTOR: RES,10.0K OHMS,1.0%,1/16W, 0402; AGILE_LINK: http://sj-agile9app/Agile/PLMServlet?action=OpenEmailObject&classid=10000&objid=146548997; Item Num: A93548-034; LIFECYCLE_PHASE: Active; Lead Free Status: No; MFR_LIFECYCLE: Active; Manufacturer: Panasonic; Manufacturer Part Num: ERJ-2RKF1002X; Num Pins: 2; PART_SUBCLASS: RESISTORS; POWER: 1/16W; RoHS Compliant: Yes; TOLERANCE: 1%
R6191 = RESISTOR: RES,4.70K OHMS,1.0%,1/16W,0402; AGILE_LINK: http://sj-agile9app/Agile/PLMServlet?action=OpenEmailObject&classid=10000&objid=146753272; Item Num: A93548-517; LIFECYCLE_PHASE: Active; Lead Free Status: No; MFR_LIFECYCLE: Active; Manufacturer: Vishay; Manufacturer Part Num: CRCW04024K70FKED; Manufacturer's Part No.: CRCW04024K70FKED; Num Pins: 2; PART_SUBCLASS: RESISTORS; POWER: 1/16W; RoHS Compliant: Yes; TOLERANCE: 1%
R6174-R6176 R6216 R6217 = Resistor,_0402: RES,10.0K OHMS,1.0%,1/16W, 0402; Agile Part Number: P02-17688R; Item Num: K28115-001; Manufacturer: Panasonic; Manufacturer Part Num: ERJ-2RKF1002X; Part Number: ERJ-2RKF1002X; Power: 1/16W; TOLERANCE: ± 1%
U105 = MAX3002EUP+T: IC TRNSLTR BIDIRECTIONAL 20TSSOP; IPN: G13285-001; Item Num: G13285-001; Manufacturer: Texa Instrument
U106 = MAX3002EUP+T: IC TRNSLTR BIDIRECTIONAL 20TSSOP; Item Num: G13285-001; Manufacturer: Texa Instrument
U141 = TCA9517A: IC I2C BUS REP LVL-TRANSL 8VSSOP; Item Num: K21773-001; Manufacturer: Texas instruments
C7558 C7559 C7561 C7562 = Cap,_NP,_0402: CAP CER 4.7UF 10V X5R 0402; Agile Part Number: P03-17662R; Dielectric: X5R; Item Num: J89506-001; Manufacturer: TDK Electronics; Manufacturer Part Num: C1005X5R1A475K050BE; Part Number: C1005X5R1A475K050BE; RATED_VOLTAGE: 10V; TOLERANCE: ±10%; Voltage: 10V
C7560 C7563 = Cap_10000PF_50V_0402: CAP - CERAMIC, 10nF, 0402, 50V, Y5V; Item Num: K30697-001; Manufacturer Part Num: GRM155F51H103Z; RATED_VOLTAGE: 50V
C7564 C7565 C7719 = Cap,_NP,_1206: CAP - CER, 22UF, 25V, 10%, X5R, 1206; Item Num: K28232-001; Manufacturer: Murata; Manufacturer Part Num: GRM31CR61E226KE15L; RATED_VOLTAGE: 25V
C7566 = Cap,_NP,_0402: CAP, CERAMIC, 100pF, 0402, 5%, 50VDC, NPO; Item Num: K13768-001; Manufacturer: Murata; Manufacturer Part Num: GRM1555C1H101JA01D; RATED_VOLTAGE: 50V
C7567 = Cap,_NP,_0402: CAPC,X7R,0402,22nf,25v,+/-10%; Item Num: A36096-192; Manufacturer: YAGEO CORP; Manufacturer Part Num: CC0402KRX7R8BB223; Part Number: CC0402KRX7R8BB223; RATED_VOLTAGE: 25V
C7568 = Cap,_NP,_0402: CAPC,X7R,0402,1NF,25V,+/-10%; Item Num: D82817-001; Manufacturer: KEMET; Manufacturer Part Num: GRM1555C1H101JA01D; Part Number: C0402C102K3RAC; RATED_VOLTAGE: 25V; TOLERANCE: +/-10%
C7569 = CAP: CAP, CERAMIC, 3300PF, 10%, 50V, X7R, 0402; AGILE_LINK: http://sj-agile9app/Agile/PLMServlet?action=OpenEmailObject&classid=10000&objid=257002141; Item Num: K13754-001; LIFECYCLE_PHASE: Active; Lead Free Status: Lead Free; MFR_LIFECYCLE: Active; Manufacturer: Murata; Manufacturer Part Num: GRM155F51H332ZA01x; Num Pins: 2; PART_SUBCLASS: CAPACITORS; RATED_VOLTAGE: 50V; RoHS Compliant: RoHS Compliant; TOLERANCE: +/-10%
C7718 = CAP: CAP, CERAMIC, 3300PF, 10%, 50V, X7R, 0402; AGILE_LINK: http://sj-agile9app/Agile/PLMServlet?action=OpenEmailObject&classid=10000&objid=257002141; CAPACITANCE: 3.3nF; Item Num: K13754-001; LIFECYCLE_PHASE: Active; Lead Free Status: Lead Free; MFR_LIFECYCLE: Active; Manufacturer: Murata; Manufacturer Part Num: GRM155F51H332ZA01x; Num Pins: 2; PART_SUBCLASS: CAPACITORS; RATED_VOLTAGE: 50V; RoHS Compliant: RoHS Compliant; TOLERANCE: +/-10%
L26 = INDUCTOR_IRON: INDCT,1.00UH,2.6A,37.00MOHM,DRUM,SM; Item Num: D23343-007; Manufacturer: Vishay Dale
R6048 = RESISTOR: RES D,0402,6.65K OHM,1%,1/16W; AGILE_LINK: http://sj-agile9app/Agile/PLMServlet?action=OpenEmailObject&classid=10000&objid=146548997; Item Num: C59249-001; LIFECYCLE_PHASE: Active; Lead Free Status: No; MFR_LIFECYCLE: Active; Manufacturer: PANASONIC INDUSTRIAL INC.; Manufacturer Part Num: ERJ-2RKF6651X; Num Pins: 2; PART_SUBCLASS: RESISTORS; POWER: 1/16W; RESISTANCE: 10.0K; RoHS Compliant: Yes; TOLERANCE: ± 1%
R6049 = RESISTOR: RES,10.0K OHMS,1.0%,1/16W, 0402; AGILE_LINK: http://sj-agile9app/Agile/PLMServlet?action=OpenEmailObject&classid=10000&objid=146548997; Item Num: K28115-001; LIFECYCLE_PHASE: Active; Lead Free Status: No; MFR_LIFECYCLE: Active; Manufacturer: Panasonic; Manufacturer Part Num: ERJ-2RKF1002X; Num Pins: 2; PART_SUBCLASS: RESISTORS; POWER: 1/16W; RESISTANCE: 10K; RoHS Compliant: Yes; TOLERANCE: ± 1%
R6050 = RESISTOR: RES, THICK FILM, 1.2 OHM, 1%, 0.1W, -100 TO +600PPM/K, 0402, SMD; AGILE_LINK: http://sj-agile9app/Agile/PLMServlet?action=OpenEmailObject&classid=10000&objid=146548997; Item Num: M85302-001; LIFECYCLE_PHASE: Active; Lead Free Status: No; MFR_LIFECYCLE: Active; Manufacturer: PANASONIC; Manufacturer Part Num: ERJ-U02F1R20X; Num Pins: 2; PART_NUMBER: ERJ-U02F1R20X; PART_SUBCLASS: RESISTORS; POWER: 1/16W; RoHS Compliant: Yes; TOLERANCE: ± 1%; VOLTAGE: NA; WATTAGE: 0.1W
R6051 = Resistor,_0402: RES 2.32K 1 % 1/16W 0402,; Agile Part Number: P02-17688R; Item Num: H83064-001; Manufacturer: CAL-CHIP ELECTRONICS; Manufacturer Part Num: RM04F2321CT-LF; Part Number: RM04F2321CT-LF; Power: 1/16W; TOLERANCE: ± 1%
R6260 = RESISTOR: RES D,0402,0.00 OHM,5.00%,1/16W; Altera Part No.: P02-14020R; Item Num: A93549-001; LIFECYCLE_PHASE: Active; Lead Free Status: No; MFR_LIFECYCLE: Active; Manufacturer: YAGEO CORP.; Manufacturer Part Num: RC0402JR-070RL; Num Pins: 2; PART_SUBCLASS: RESISTORS; POWER: 1/16W; Part Class: RESISTORS; Price: 0; RESISTANCE: 0; RoHS Compliant: RoHS Compliant; Tolerance: ± 5%
ST28 = SHORT
TP995-TP997 = TP,_0.016_,_Thru_Hole
U129 = MAX15053EWL+T: Item Num: J96655-001; Manufacturer Part Num: MAX15053EWL+
U130 U131 = ADP1752ACPZ-1.0-R7: Item Num: M76709-001

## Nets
GND: C416.1 C417.2 C418.2 C419.2 C420.2 C421.2 C422.2 C423.2 C424.2 C498.2 C1019.2 C1020.2 C1021.2 C1022.2 C1023.2 C1024.2 C1025.2 C1026.2 C1027.2 C1028.2 C1029.2 C1030.2 C1031.2 C1032.2 C1033.2 C1034.1 C1035.1 C1036.1 C1037.2 C1038.2 C1039.2 C1040.2 C1041.1 C1042.1 C1044.2 C1045.2 C1046.2 C1047.2 C1048.2 C1049.2 C1050.2 C1051.2 C1052.2 C1053.2 C1054.2 C1055.2 C1056.2 C1057.2 C1058.2 C1059.2 C1060.2 C1061.2 C1062.2 C1063.2 C1064.2 C1065.2 C1066.2 C1067.2 C1068.2 C1069.2 C1070.2 C1090.2 C1091.2 C1092.2 C1093.2 C1094.2 C1095.2 C1096.2 C1097.2 C1098.2 C1099.2 C1100.2 C1101.2 C1102.2 C1103.2 C1104.2 C1105.2 C1106.2 C1107.2 C1108.2 C1109.2 C1110.2 C1111.2 C1112.2 C1113.2 C1114.2 C1115.2 C1116.2 C1117.2 C1118.2 C1119.2 C1120.2 C1121.2 C1122.2 C1123.2 C1124.2 C1125.2 C1126.2 C1127.2 C1128.2 C1129.2 C1130.2 C1131.2 C1132.2 C1133.2 C1134.2 C1135.1 C1136.1 C1137.1 C1138.1 C1139.1 C1140.1 C1141.1 C1142.1 C1143.1 C1144.1 C1145.1 C1146.1 C1147.1 C1148.1 C1149.1 C1150.1 C1151.1 C1152.1 C1153.1 C1154.1 C1155.1 C1159.1 C1160.1 C1161.2 C1162.1 C1163.1 C1164.2 C1165.1 C1166.1 C1167.2 C1168.1 C1169.1 C1170.1 C1171.1 C1172.1 C1173.1 C1174.1 C1175.1 C1176.1 C1177.1 C1178.1 C1179.1 C1180.2 C1181.2 C1182.2 C1183.2 C1184.2 C1185.2 C1186.2 C1187.2 C1188.2 C1189.1 C1190.2 C1191.2 C1192.2 C1193.2 C1194.1 C1195.2 C1196.2 C1197.2 C1198.2 C1199.1 C1200.2 C1201.2 C1202.2 C1203.2 C1204.1 C1205.2 C1208.2 C1209.2 C1210.2 C1211.1 C1212.2 C1213.2 C1214.2 C1215.2 C1216.1 C1217.2 C1218.2 C1219.2 C1220.2 C1221.1 C1222.2 C1223.2 C1224.2 C1225.2 C1226.1 C1227.2 C1232.1 C1233.1 C1234.1 C1235.1 C1236.1 C1237.1 C1238.1 C1239.2 C1240.2 C1241.2 C1242.2 C1243.2 C1244.1 C1245.1 C1246.2 C1247.2 C1248.2 C1249.2 C1250.2 C1251.2 C1255.1 C1256.1 C1257.1 C1258.1 C1259.1 C1260.1 C1261.1 C1262.1 C1265.1 C1266.2 C1267.1 C1268.1 C1269.1 C1270.1 C1277.2 C1283.1 C1284.2 C1314.2 C1315.2 C1316.2 C1317.2 C1318.2 C1319.2 C1320.2 C1321.2 C1322.2 C1323.2 C1324.2 C1325.2 C1326.2 C1401.2 C1402.2 C1403.2 C1404.2 C1405.2 C1406.2 C1407.2 C1408.2 C1409.2 C1410.2 C1411.2 C1412.2 C1413.2 C1414.2 C1415.2 C1416.2 C1417.2 C1418.2 C1419.2 C1420.2 C1421.2 C1422.2 C1423.2 C1424.2 C1425.2 C1426.2 C1427.2 C1428.2 C1429.2 C1430.2 C1431.2 C1432.2 C1433.2 C1435.2 C1436.2 C1437.2 C1438.2 C1439.2 C1440.2 C1441.2 C1442.2 C1443.2 C1444.2 C1445.2 C1446.2 C1447.2 C1448.2 C1449.2 C1450.1 C7399.2 C7400.2 C7401.1 C7402.2 C7435.2 C7436.2 C7437.2 C7438.2 C7558.1 C7559.1 C7560.2 C7561.1 C7562.1 C7563.2 C7564.1 C7565.1 C7568.2 C7575.1 C7719.1 ST28.1 U105.11(GND) U106.11(GND) U129.A1(GND) U130.6(GND) U130.17(EPAD) U131.6(GND) U131.17(EPAD) U141.4(GND) ; also on sheet 9 10 11 13 14 15 16 17 18 19 20 21 22 23 25 26 27 28 29 30 31 32 33 34 35 36 38 39 40 41 42 43 44 45 46 47 48 49 50 51 52 53 54 55 56 57 58 59 60 61 62 63 64 65 66 67 68 69 70 71 72 73
VCCA_PLL_FLTR: C1135.2 C1136.2 C1137.2 C1138.2 C1139.2 C1140.2 C1141.2 C1142.2 C1143.2 ; also on sheet 39 59
VCCCLK_GXR_EN: R6260.1 U129.B3(EN) ; also on sheet 51
VCCCLK_GXR_PG: R6174.2 U129.C3(PGOOD) ; also on sheet 49
VCCFUSE_GXR_PG: R6176.2 U131.5(PG) ; also on sheet 50
VCCFUSEWR_GXF: C7559.2 TP997.1 U130.9(SENSE) U130.10(VOUT1) U130.11(VOUT2) U130.12(VOUT3) U130.13(VOUT4) U130.14(VOUT5) ; also on sheet 38
VCCFUSEWR_GXF_PG: R6175.2 U130.5(PG) ; also on sheet 50
VCCFUSEWR_SDM: C416.2 C1284.1 ; also on sheet 39 69
VCCH_FGT_GXF: C1249.1 C1250.1 C1251.1 ; also on sheet 38 39
VCCPLLDIG_HPS: C1244.2 C1245.2 ; also on sheet 38
VCCPLLDIG_SDM: C1269.2 C1270.2 ; also on sheet 38 65
VCCR_CORE: C1165.2 C1166.2 C1167.1 ; also on sheet 39 59
0p6V_VREF_DDR4_CH01: C417.1 C418.1 C419.1 C420.1 ; also on sheet 9 10 11 14 15 16 39 72
0p6V_VREF_DDR4_CH2: C7435.1 C7436.1 C7437.1 C7438.1 ; also on sheet 20 39 72
0p6V_VREF_DDR4_CH3: C421.1 C422.1 C423.1 C424.1 ; also on sheet 19 39 72
0p8V_VCC_HSSI_GXF: C1034.2 C1035.2 C1036.2 C1041.2 C1042.2 C1045.1 C1046.1 C1047.1 C1058.1 C1059.1 C1060.1 C1061.1 C1062.1 ; also on sheet 38 65
0p8V_VCCH: C1144.2 C1145.2 C1146.2 C1147.2 C1148.2 C1149.2 C1150.2 C1151.2 C1152.2 C1153.2 C1154.2 C1155.2 C1168.2 C1169.2 C1170.2 C1171.2 C1172.2 C1173.2 C1174.2 C1175.2 C1176.2 C1177.2 C1178.2 C1179.2 C1180.1 C1181.1 C1182.1 C1183.1 C1184.1 C1185.1 C1449.1 ; also on sheet 38 64
0p9V_VCC_HSSI_GXR: C1121.1 C1122.1 C1123.1 C1124.1 C1125.1 C1126.1 C1127.1 C1267.2 C1268.2 C1314.1 C1315.1 C1316.1 C1317.1 C1318.1 C1319.1 C1448.1 ; also on sheet 38 63
0p9V_VCCED_GXR: C1114.1 C1115.1 C1116.1 C1320.1 ; also on sheet 38 60
0p9V_VCCL_HPS: C1094.1 C1095.1 C1096.1 C1097.1 C1265.2 C1266.1 ; also on sheet 38 60
1p0V_VCCCLK_GXR: C1246.1 C1247.1 C1248.1 C7565.2 C7566.1 C7719.2 L26.2 R6048.1 TP995.1 ; also on sheet 31 33 38
1p0V_VCCERT_FGT_GXF: C1098.1 C1099.1 C1100.1 C1101.1 C1102.1 C1103.1 C1104.1 ; also on sheet 38 61
1p0V_VCCFUSE_GXR: C7562.2 TP996.1 U131.9(SENSE) U131.10(VOUT1) U131.11(VOUT2) U131.12(VOUT3) U131.13(VOUT4) U131.14(VOUT5) ; also on sheet 38
1p0V_VCCFUSE_GXR_EN: U130.4(EN) U131.4(EN) ; also on sheet 51
1p0V_VCCRT_GXR: C1128.1 C1129.1 C1130.1 C1131.1 C1132.1 C1133.1 C1134.1 C1277.1 C1321.1 C1322.1 C1323.1 C1324.1 C1326.1 C1447.1 ; also on sheet 38 62
1p2V_DDR4_CH01: C1208.1 C1209.1 C1210.1 C1211.2 C1212.1 C1213.1 C1214.1 C1215.1 C1216.2 C1217.1 C1218.1 C1219.1 C1220.1 C1221.2 C1222.1 C1223.1 C1224.1 C1225.1 C1226.2 C1227.1 C7399.1 C7401.2 R2707.1 R2714.1 R6216.2 R6217.1 U105.2(VL) U106.2(VL) ; also on sheet 9 10 11 14 15 16 32 39 46 47 52 70 72
1p2V_DDR4_CH2: C1186.1 C1187.1 C1188.1 C1189.2 C1190.1 C1191.1 C1192.1 C1193.1 C1194.2 C1195.1 C1196.1 C1197.1 C1198.1 C1199.2 C1200.1 C1201.1 C1202.1 C1203.1 C1204.2 C1205.1 C1255.2 C1256.2 ; also on sheet 19 20 30 39 71 72
1p8V: C1232.2 C1233.2 C1234.2 C1235.2 C1236.2 C1237.2 C1238.2 C1239.1 C1240.1 C1241.1 C1242.1 C1243.1 ; also on sheet 39 66
1p8V_FLTR: C1257.2 C1258.2 C1259.2 C1260.2 C1261.2 C1262.2 ; also on sheet 39
1p8v_MAIN_I2C_SCL: R6057.1 U141.2(SCL_A) ; also on sheet 36 50
1p8v_MAIN_I2C_SDA: R6058.1 U141.3(SDA_A) ; also on sheet 36 49
1p8V_VCCH_GXR: C1111.1 C1112.1 C1113.1 C1325.1 ; also on sheet 38 39
3p3V: C7558.2 C7561.2 C7564.2 R6174.1 R6175.1 R6176.1 U129.A3(IN) U130.1(VIN1) U130.2(VIN2) U130.3(VIN3) U130.15(VIN4) U130.16(VIN5) U131.1(VIN1) U131.2(VIN2) U131.3(VIN3) U131.15(VIN4) U131.16(VIN5) ; also on sheet 54 58 59 63 65 66 67 69 70 71 72 73
3p3V_STBY: C7400.1 C7402.1 C7575.2 R6059.2 R6060.2 R6061.2 R6191.2 U105.19(VCC) U106.19(VCC) U141.8(VCCB) ; also on sheet 30 44 48 49 50 51 52 53 57
6301_AGND: C7567.2 C7569.2 C7718.2 R6049.1 ST28.2
B_M10_CRC_ERROR: U105.8(IO_VL7) ; also on sheet 22
FPGA_M10_IBUS_CLK0: U106.15(IO_VCC5) ; also on sheet 51
FPGA_M10_IBUS_CLK1: U105.20(IO_VCC1) ; also on sheet 49
FPGA_M10_IBUS_CS0_N: U106.12(IO_VCC8) ; also on sheet 49
FPGA_M10_IBUS_CS1_N: U105.16(IO_VCC4) ; also on sheet 51
FPGA_M10_MISO_0: U106.13(IO_VCC7) ; also on sheet 49
FPGA_M10_MISO_1: U105.17(IO_VCC3) ; also on sheet 51
FPGA_M10_MOSI_0: U106.14(IO_VCC6) ; also on sheet 51
FPGA_M10_MOSI_1: U105.18(IO_VCC2) ; also on sheet 51
FPGA_M10_VID_ALERTN: R6217.2 U106.4(IO_VL3) ; also on sheet 22
FPGA_SEU_ERROR: U105.14(IO_VCC6) ; also on sheet 48
FPGA_SEU_ERROR_B: R6216.1 U105.7(IO_VL6) ; also on sheet 22
FPGA_VCC: C1019.1 C1020.1 C1021.1 C1022.1 C1023.1 C1024.1 C1025.1 C1026.1 C1027.1 C1028.1 C1029.1 C1030.1 C1031.1 C1032.1 C1033.1 C1037.1 C1038.1 C1039.1 C1040.1 C1044.1 C1048.1 C1049.1 C1050.1 C1051.1 C1052.1 C1053.1 C1054.1 C1055.1 C1056.1 C1057.1 C1063.1 C1064.1 C1065.1 C1066.1 C1067.1 C1068.1 C1069.1 C1070.1 C1090.1 C1091.1 C1092.1 C1093.1 C1105.1 C1106.1 C1107.1 C1108.1 C1109.1 C1110.1 C1117.1 C1118.1 C1119.1 C1120.1 C1401.1 C1402.1 C1403.1 C1404.1 C1405.1 C1406.1 C1407.1 C1408.1 C1409.1 C1410.1 C1411.1 C1412.1 C1413.1 C1414.1 C1415.1 C1416.1 C1417.1 C1418.1 C1419.1 C1420.1 C1421.1 C1422.1 C1423.1 C1424.1 C1425.1 C1426.1 C1427.1 C1428.1 C1429.1 C1430.1 C1431.1 C1432.1 C1433.1 C1435.1 C1436.1 C1437.1 C1438.1 C1439.1 C1440.1 C1441.1 C1442.1 C1443.1 C1444.1 C1445.1 C1446.1 C1450.2 ; also on sheet 37 55 56
FPGA_VID_ALERTN: U106.17(IO_VCC3) ; also on sheet 51
IO_1p8V: C498.1 C1159.2 C1160.2 C1161.1 C1162.2 C1163.2 C1164.1 C1283.2 R6057.2 R6058.2 U141.1(VCCA) ; also on sheet 35 36 39 43 44 46 67
M10_CRC_ERROR: R6191.1 U105.13(IO_VCC7) ; also on sheet 51
M10_IBUS_CLK0: U106.6(IO_VL5) ; also on sheet 22
M10_IBUS_CLK1: U105.1(IO_VL1) ; also on sheet 22
M10_IBUS_CS0_N: U106.9(IO_VL8) ; also on sheet 22
M10_IBUS_CS1_N: U105.5(IO_VL4) ; also on sheet 22
M10_MISO_0: U106.8(IO_VL7) ; also on sheet 22
M10_MISO_1: U105.4(IO_VL3) ; also on sheet 22
M10_MOSI_0: U106.7(IO_VL6) ; also on sheet 22
M10_MOSI_1: U105.3(IO_VL2) ; also on sheet 22
MAIN_I2C_SCL: R6060.1 U141.7(SCL_B) ; also on sheet 43 44 46 63
MAIN_I2C_SDA: R6059.1 U141.6(SDA_B) ; also on sheet 43 44 46 63
N47866759: C7563.1 U131.7(SS)
N47871117: C7718.1 R6051.1 U129.B1(COMP)
N47871122: C7569.1 R6051.2
N47871485: C7566.2 R6048.2 R6049.2 U129.C1(FB)
N47872099: L26.1 R6050.1 U129.A2(LX)
N47874483: C7567.1 U129.C2(SS/REFIN)
N48350242: R6061.1 U141.5(EN)
N48490558: C7560.1 U130.7(SS)
N49281976: R2707.2 U105.10(EN)
N49308651: R2714.2 U106.10(EN)
N49972833: R6260.2 U129.B2(SKIP)
N50603874: C7568.1 R6050.2

Not connected (* = marked no-connect by the designer): U105 6(IO_VL5)* 9(IO_VL8)* 12(IO_VCC8)* 15(IO_VCC5)*; U106 1(IO_VL1)* 3(IO_VL2)* 5(IO_VL4)* 16(IO_VCC4)* 18(IO_VCC2)* 20(IO_VCC1)*; U130 8(NC)*; U131 8(NC)*

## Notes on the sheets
sheet 74
- PWR - VCCCLK_GXR, VCCFUSEWR_GXF, VCCFUSE_GXR
- 1.0V
- 1.0V
- 1.0V
sheet 75
- Decoupling - page 1
- Bottom side
- Bottom side
- Place under VCCL_SDM pins
- FPGA Periphery
- Bottom side
- FPGA Periphery
- 0.9V
- 0.8V
- Bottom side
- FPGA Periphery
- 1.0V
- Bottom side
- FPGA Periphery
- Bottom side
- FPGA Periphery
- 0.9V
- 1.8V
- FPGA Periphery
- Bottom side
- FPGA Periphery
- FPGA Periphery
- Bottom side
- FPGA Periphery
- 0.9V
- Place under VCCH_SDM pins
- Bottom side
- FPGA Periphery
- 1.0V
- 0.8V
- Bottom side
- 0.9V
- 1.2V
- Bottom side
- FPGA Periphery
- Bottom side
- FPGA Periphery
- Bottom side
- FPGA Periphery
- Bottom side
- 0201
- 0201
- 1.8V
- 1.8V
- 1.2V
- Place under VCCBAT
- Place under VCCIO_HPS
- Place under VCCIO_SDM
- For FM85 DEVKIT ONLY
- C1165, C1166 : 4.7uF
- C1167 : DNI
- FPGA Periphery
- Note:  Bottom side = Place under the FPGA in the pin field area
- FPGA Periphery = Place near FPGA on the top side
- 0.8V
sheet 76
- Decoupling - page 2
- Bottom side
- FPGA Periphery
- Bottom side
- FPGA Periphery
- Bottom side
- FPGA Periphery
- Bottom side
- FPGA Periphery
- Place under VCCIO_PIO_2B
- Place under VCCIO_PIO_2E
- Place under VCCIO_PIO_2F
- Place under VCCIO_PIO_2C
- Bottom side
- FPGA Periphery
- Bottom side
- FPGA Periphery
- Bottom side
- FPGA Periphery
- Bottom side
- FPGA Periphery
- Place under VCCIO_PIO_3A
- Place under VCCIO_PIO_3B
- Place under VCCIO_PIO_3C
- Place under VCCIO_PIO_3D
- Bottom side
- FPGA Periphery
- Bottom side
- Bottom side
- Bottom side
- Bottom side
- Place under VCCPT pins
- 0.9V
- 1.8V
- 1.0V
- Place under VCCIO_PIO_SDM pin
- Bottom side
- Bottom side
- Bottom side
- Bottom side
- FPGA Periphery
- Bottom side
- Bottom side
- Bottom side
- 0.9V
- Place under VCCADC pins
- Place under VCCPLL_SDM pins
- Place under VCCPLL_HPS pins
- Bottom side
- Note:  Bottom side = Place under the FPGA in the pin field area
- FPGA Periphery = Place near FPGA on the top side
sheet 77
- Level Shifter
- Decoupling Caps
- VCCA = 0.9V - 5.5V
- VCCB = 2.7V - 5.5V
- Bottom side
- In the Cavity
- Near the VR
- In the Peripheral
